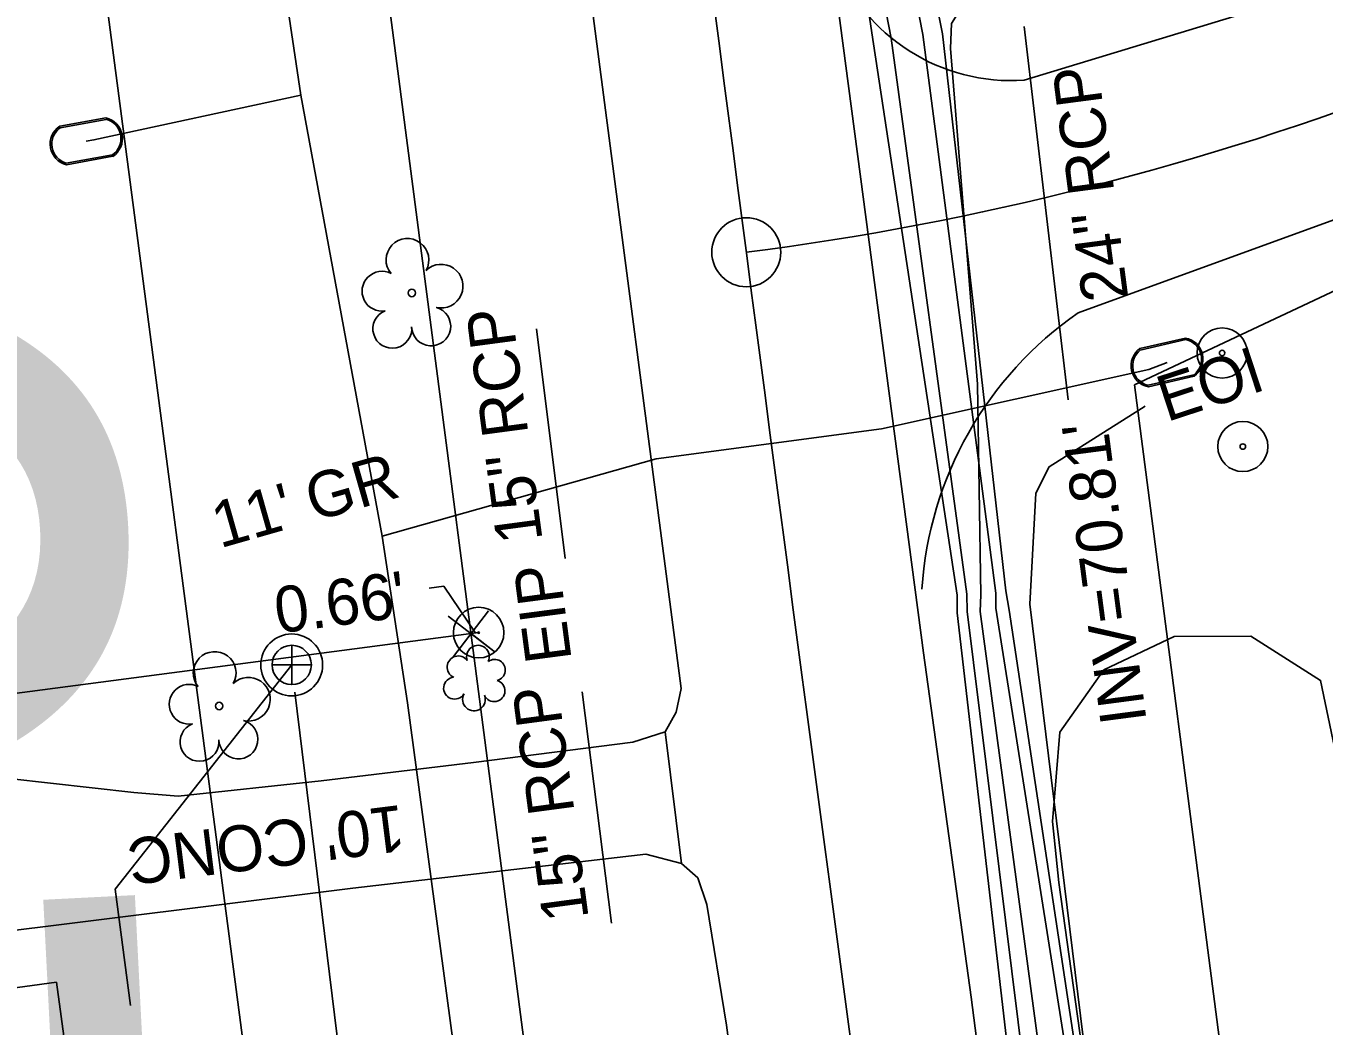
# Model space of a CAD drawing. Extents: x 2364404 to 2371833, y 798876 to 809754.
# Drawn here: x 2368460.1 to 2368573.1, y 806788.8 to 806875.8 of the extents above; entities that cross this region are included whole.
import ezdxf

# ---------------------------------------------------------------- set-up
doc = ezdxf.new("R2010")
doc.units = 0
for name, color, linetype in [('Exist Building', 7, 'Continuous'), ('Exist Horizontal Alignment Direction Label', 7, 'Continuous'), ('Exist Horizontal Alignment Point', 7, 'Continuous'), ('Exist Other Culture Located Object CELL', 7, 'Continuous'), ('Exist Property Corner CELL', 7, 'Continuous'), ('Exist Property Iron Pin CELL', 7, 'Continuous'), ('Exist Property Iron Pin Text', 7, 'Continuous'), ('Exist Property Line', 7, 'Continuous'), ('Exist Property Line Leader', 7, 'Continuous'), ('Exist Property Line Text', 7, 'Continuous'), ('Exist Right of Way Easement Line', 7, 'Continuous'), ('Exist Right of Way Line', 7, 'Continuous'), ('Exist Roads EOP', 7, 'Continuous'), ('Exist Roads EOP Other', 7, 'Continuous'), ('Exist Roads EOP Other Text', 7, 'Continuous'), ('Exist Roads Soil', 7, 'Continuous'), ('Exist Roads Soil Text', 7, 'Continuous'), ('Exist Structure Minor Pipes RCP 15 Inch', 7, 'Continuous'), ('Exist Structure Minor Pipes RCP 15 Inch Text', 7, 'Continuous'), ('Exist Structure Minor Pipes RCP 24 Inch', 7, 'Continuous'), ('Exist Structure Minor Pipes RCP 24 Inch Invert', 7, 'Continuous'), ('Exist Structure Minor Pipes RCP 24 Inch Text', 7, 'Continuous'), ('Exist Utilities Gas UG Line SUE LOS B', 7, 'Continuous'), ('Exist Utilities Other Located Object CELL', 7, 'Continuous'), ('Exist Utilities Sanitary Sewer Manhole CELL', 7, 'Continuous'), ('Exist Utilities Sanitary Sewer Manhole Leader', 7, 'Continuous'), ('Exist Utilities Sanitary Sewer UG Line', 7, 'Continuous'), ('Exist Utilities Telephone UG Cable SUE LOS C', 7, 'Continuous'), ('Exist Utilities Telephone UG Cable SUE LOS C Text', 7, 'Continuous'), ('Exist Utilities Telephone UG FO SUE LOS B', 7, 'Continuous'), ('Exist Utilities Telephone UG FO SUE LOS D', 7, 'Continuous'), ('Exist Utilities TV UG Cable SUE LOS B', 7, 'Continuous'), ('Exist Utilities Water Meter CELL', 7, 'Continuous'), ('Exist Utilities Water UG Line SUE LOS B', 7, 'Continuous'), ('Exist Vegetation Shrub CELL', 7, 'Continuous'), ('Exist Vegetation Tree CELL', 7, 'Continuous'), ('Exist Vegetation Woods Line', 7, 'Continuous'), ('Prop Horizontal Alignment', 7, 'Continuous')]:
    doc.layers.add(name, color=color, linetype=linetype)

msp = doc.modelspace()

# ---------------------------------------------------------------- linework, layer by layer
at = {"layer": 'Exist Building'}
msp.add_lwpolyline([(2368438.39, 806735.97), (2368431.21, 806788.32), (2368462.79, 806792.65), (2368466.23, 806767.5), (2368461.22, 806766.81), (2368464.95, 806739.61)], close=True, dxfattribs=at)
at = {"layer": 'Exist Horizontal Alignment Point'}
msp.add_circle((2368522.8, 806856.13), 3, dxfattribs=at)
at = {"layer": 'Exist Other Culture Located Object CELL'}
for radius in [2.18, 0.24]:
    msp.add_circle((2368565.99, 806839.23), radius, dxfattribs=at)
at = {"layer": 'Exist Property Corner CELL'}
msp.add_line((2368498.87, 806822.96), (2368498.87, 806822.96), dxfattribs=at)
msp.add_lwpolyline([(2368500.39, 806824.94), (2368497.34, 806820.98), (2368498.87, 806822.96), (2368500.85, 806821.44), (2368496.88, 806824.48)], dxfattribs=at)
at = {"layer": 'Exist Property Iron Pin CELL'}
for radius in [2.2, 0.0707]:
    msp.add_circle((2368499.52, 806823.05), radius, dxfattribs=at)
at = {"layer": 'Exist Property Line'}
for p, q in [((2368333.99, 806801.31), (2368498.87, 806822.96)), ((2368498.87, 806822.96), (2368499.52, 806823.05))]:
    msp.add_line(p, q, dxfattribs=at)
at = {"layer": 'Exist Property Line Leader'}
msp.add_lwpolyline([(2368499.22, 806823.05), (2368496.48, 806827.1), (2368495.21, 806826.93)], dxfattribs=at)
at = {"layer": 'Exist Right of Way Easement Line'}
msp.add_line((2368511.71, 806538.64), (2368344.2, 807814.14), dxfattribs=at)
at = {"layer": 'Exist Right of Way Line'}
for p, q in [((2368533.02, 806560.45), (2368368.2, 807827.36)), ((2368556.56, 806844.6), (2369018.27, 807061.53)), ((2368619.17, 806363.33), (2368556.56, 806844.6))]:
    msp.add_line(p, q, dxfattribs=at)
at = {"layer": 'Exist Roads EOP'}
for points in [[(2368562.93, 806637.46), (2368555.74, 806690.75), (2368548.61, 806742.82), (2368542.36, 806791.34), (2368538.21, 806821.28), (2368530.22, 806881.79), (2368518.49, 806971.03), (2368511.29, 807026.45), (2368505.76, 807074.75), (2368500.82, 807111.79), (2368494.06, 807163.04), (2368486.21, 807225.24), (2368486.94, 807228.44), (2368484.21, 807253.24), (2368481.5, 807263.09), (2368479.96, 807275.52), (2368472.82, 807329.17)], [(2368542.08, 806633.94), (2368537.65, 806665.16), (2368536.24, 806665.79), (2368533.02, 806685.33), (2368534.76, 806687.62), (2368527.71, 806739.03), (2368521.09, 806788.9), (2368519.37, 806799.41), (2368518.6, 806801.72), (2368517.16, 806802.97), (2368515.73, 806814.41), (2368516.71, 806816.13), (2368517.13, 806818.19), (2368509.17, 806879.16), (2368497.78, 806964.4), (2368495.51, 806965.25), (2368493.89, 806981.12), (2368495.71, 806983.28), (2368490.79, 807023.19), (2368488.57, 807040.03)]]:
    msp.add_lwpolyline(points, dxfattribs=at)
at = {"layer": 'Exist Roads EOP Other'}
msp.add_line((2368514.07, 806803.78), (2368517.16, 806802.97), dxfattribs=at)
for points in [[(2368515.73, 806814.41), (2368512.94, 806813.51), (2368499.07, 806811.77), (2368485.81, 806810.15), (2368473.38, 806808.82), (2368469.54, 806809.14), (2368458.64, 806810.35), (2368453.39, 806810.8), (2368445.02, 806809.89), (2368429.46, 806807.35)], [(2368514.07, 806803.78), (2368505.33, 806802.78), (2368488.59, 806800.83), (2368455.28, 806796.67), (2368455.88, 806791.71)]]:
    msp.add_lwpolyline(points, dxfattribs=at)
at = {"layer": 'Exist Roads Soil'}
for points in [[(2368546.98, 806871.09), (2368590.6, 806884.38), (2368636.02, 806903.12), (2368685.77, 806924.3), (2368729.9, 806945.5)], [(2368551.68, 806850.87), (2368596.14, 806867.04), (2368645.06, 806889.19), (2368692.28, 806909.13), (2368738.29, 806929.75)]]:
    msp.add_lwpolyline(points, dxfattribs=at)
for centre, radius, start, end in [((2368545.85, 806887.56), 16.51, 200.905, 273.9339), ((2368569.76, 806824.77), 31.75, 124.7105, 176.283)]:
    msp.add_arc(centre, radius, start, end, dxfattribs=at)
at = {"layer": 'Exist Structure Minor Pipes RCP 15 Inch'}
for p, q in [((2368507.04, 806829.5), (2368504.55, 806849.46)), ((2368511.09, 806797.77), (2368508.52, 806817.89))]:
    msp.add_line(p, q, dxfattribs=at)
at = {"layer": 'Exist Structure Minor Pipes RCP 24 Inch'}
msp.add_line((2368546.96, 806875.77), (2368550.79, 806843.3), dxfattribs=at)
at = {"layer": 'Exist Utilities Gas UG Line SUE LOS B'}
msp.add_lwpolyline([(2368565.51, 806627.35), (2368559.18, 806675.74), (2368554.09, 806719.63), (2368549.98, 806751.76), (2368546.89, 806775.18), (2368541.13, 806824.77), (2368541.15, 806826.3), (2368533.73, 806875.2), (2368530.25, 806898.57), (2368522.83, 806953.25), (2368520.6, 806972.93), (2368514.47, 807022.15), (2368508.12, 807071.69), (2368503.05, 807109.35), (2368503.04, 807109.39), (2368501.76, 807120.55), (2368495.27, 807170.09), (2368488.83, 807219.75), (2368482.33, 807269.18), (2368476.59, 807310.66)], dxfattribs=at)
at = {"layer": 'Exist Utilities Other Located Object CELL'}
for radius in [2.18, 0.24]:
    msp.add_circle((2368564.19, 806847.37), radius, dxfattribs=at)
at = {"layer": 'Exist Utilities Sanitary Sewer Manhole CELL'}
msp.add_lwpolyline([(2368483.26, 806821.95), (2368483.26, 806818.53), (2368483.26, 806820.24), (2368484.98, 806820.24), (2368481.55, 806820.24)], dxfattribs=at)
for radius in [2.69, 1.71]:
    msp.add_circle((2368483.26, 806820.24), radius, dxfattribs=at)
at = {"layer": 'Exist Utilities Sanitary Sewer Manhole Leader'}
msp.add_lwpolyline([(2368483.26, 806820.24), (2368467.91, 806800.74), (2368469.24, 806790.61)], dxfattribs=at)
at = {"layer": 'Exist Utilities Sanitary Sewer UG Line'}
msp.add_line((2368483.53, 806817.87), (2368521.16, 806511.46), dxfattribs=at)
at = {"layer": 'Exist Utilities Telephone UG Cable SUE LOS C'}
for points in [[(2368513, 806728.67), (2368513.11, 806729.23), (2368527.58, 806725.8), (2368551.81, 806727.42), (2368553.66, 806732.83), (2368554.05, 806735.47), (2368548.14, 806775.63), (2368542, 806824.9), (2368541.99, 806826.38), (2368535.41, 806874.73), (2368525.92, 806923.45), (2368519.62, 806972.71), (2368513.1, 807021.89), (2368507.14, 807071.19), (2368500.36, 807120.72), (2368487.41, 807219.56), (2368485.62, 807270.73), (2368476.5, 807319.29)], [(2368512.76, 806728.82), (2368513.23, 806728.83), (2368526.6, 806730.3), (2368554.19, 806730.87), (2368555.55, 806735.53), (2368549.73, 806775.94), (2368543.15, 806824.88), (2368543.19, 806826.35), (2368542.9, 806844.67), (2368540.57, 806873.85), (2368540.65, 806876.02), (2368542.68, 806879.28), (2368552.82, 806878.65), (2368578.3, 806883.33), (2368609.68, 806897.03), (2368634.38, 806908.76), (2368649.63, 806915.88), (2368651.51, 806917.09), (2368652, 806919.33), (2368650.03, 806922.76), (2368650.32, 806923.36)]]:
    msp.add_lwpolyline(points, dxfattribs=at)
at = {"layer": 'Exist Utilities Telephone UG FO SUE LOS B'}
msp.add_lwpolyline([(2368557.66, 806726.62), (2368552.25, 806776.28), (2368544.5, 806825.17), (2368544.52, 806826.49), (2368538.15, 806875.06), (2368528.53, 806924.12), (2368522.67, 806972.9), (2368516.86, 807022.32), (2368510.19, 807071.54), (2368510.15, 807071.85), (2368503.82, 807121.23), (2368497.45, 807169.98), (2368490.99, 807219.7), (2368486.98, 807243.03), (2368483.26, 807270.12), (2368478.16, 807319.19)], dxfattribs=at)
at = {"layer": 'Exist Utilities Telephone UG FO SUE LOS D'}
msp.add_lwpolyline([(2368570.42, 806627.22), (2368563.79, 806676.05), (2368559.26, 806726.79), (2368553, 806776.39), (2368545.68, 806825.01), (2368545.37, 806826.67), (2368539.86, 806875.13), (2368530.01, 806924.21), (2368524.34, 806972.87), (2368518.19, 807022.38), (2368511.17, 807071.48), (2368504.8, 807121.29), (2368498.76, 807170.03), (2368493.38, 807219.79), (2368488.92, 807243.04), (2368484.81, 807270.66), (2368473.51, 807368.34)], dxfattribs=at)
at = {"layer": 'Exist Utilities TV UG Cable SUE LOS B'}
msp.add_lwpolyline([(2368511.74, 806730.95), (2368526.2, 806733.08), (2368549.61, 806740.43), (2368557.41, 806743.28), (2368553.5, 806776.53), (2368547.46, 806825.52), (2368547.99, 806835.17), (2368549.16, 806837.48), (2368557.51, 806842.73)], dxfattribs=at)
at = {"layer": 'Exist Utilities Water Meter CELL'}
for p, q in [((2368465.39, 806865.78), (2368465.39, 806865.78)), ((2368559.41, 806846.55), (2368559.41, 806846.55))]:
    msp.add_line(p, q, dxfattribs=at)
for points in [[(2368463.08, 806867.09), (2368467.09, 806867.82)], [(2368463.11, 806866.95), (2368467.12, 806867.68)], [(2368467.68, 806864.61), (2368463.65, 806863.87)], [(2368467.7, 806864.48), (2368463.67, 806863.74)], [(2368557.04, 806847.75), (2368561.01, 806848.66)], [(2368557.07, 806847.62), (2368561.04, 806848.53)], [(2368561.74, 806845.48), (2368557.75, 806844.56)], [(2368561.77, 806845.35), (2368557.78, 806844.43)]]:
    msp.add_lwpolyline(points, dxfattribs=at)
for centre, radius, start, end in [((2368466.67, 806866.01), 1.86, 303.9851, 76.6451), ((2368466.68, 806866.02), 1.73, 305.4639, 75.2096), ((2368464.11, 806865.54), 1.86, 123.5148, 256.3162), ((2368464.12, 806865.54), 1.73, 125.6377, 254.1191), ((2368560.66, 806846.84), 1.86, 306.5926, 79.2527), ((2368560.68, 806846.84), 1.73, 308.0715, 77.8171), ((2368558.13, 806846.25), 1.86, 126.1223, 258.9237), ((2368558.14, 806846.25), 1.73, 128.2452, 256.7266)]:
    msp.add_arc(centre, radius, start, end, dxfattribs=at)
at = {"layer": 'Exist Utilities Water UG Line SUE LOS B'}
for points in [[(2368519.2, 806620.08), (2368510.97, 806683.25), (2368505.65, 806723.63), (2368499.9, 806767.95), (2368493.34, 806816.93), (2368491.14, 806831.44), (2368484.04, 806869.78), (2368477.82, 806911.63), (2368472.48, 806959.83), (2368471.08, 806975.35), (2368467.91, 807014.19), (2368461.16, 807070.94), (2368455.32, 807116.26), (2368449.6, 807161.65), (2368446.12, 807187.28), (2368441.35, 807211.9), (2368441.09, 807221.64), (2368437.56, 807243.96), (2368435.61, 807263.12), (2368428.93, 807315.03)], [(2368465.39, 806865.78), (2368466.06, 806865.9), (2368484.04, 806869.78)], [(2368491.14, 806831.44), (2368514.96, 806838.17), (2368534.56, 806840.77), (2368557.81, 806845.93), (2368559.41, 806846.55)]]:
    msp.add_lwpolyline(points, dxfattribs=at)
at = {"layer": 'Exist Vegetation Shrub CELL'}
msp.add_line((2368499.23, 806818.92), (2368499.23, 806818.92), dxfattribs=at)
for centre, radius, start, end in [((2368499.46, 806820.96), 0.99, 334.8391, 200.4717), ((2368497.75, 806820.05), 0.968, 35.8908, 245.4216), ((2368500.91, 806819.79), 0.929, 284.4567, 126.0861), ((2368497.43, 806818.22), 0.955, 95.1099, 327.9534), ((2368500.87, 806817.99), 0.937, 204.9913, 73.4601), ((2368499.11, 806817.24), 0.984, 151.2797, 21.387)]:
    msp.add_arc(centre, radius, start, end, dxfattribs=at)
at = {"layer": 'Exist Vegetation Tree CELL'}
for p, q in [((2368493.71, 806852.59), (2368493.71, 806852.59)), ((2368476.95, 806816.67), (2368476.95, 806816.67))]:
    msp.add_line(p, q, dxfattribs=at)
for centre in [(2368493.71, 806852.59), (2368476.95, 806816.67)]:
    msp.add_circle(centre, 0.326, dxfattribs=at)
for centre, radius, start, end in [((2368493.33, 806855.46), 1.86, 330.1651, 219.7134), ((2368491.11, 806852.74), 1.73, 62.6636, 279.3457), ((2368496.26, 806853.18), 1.9, 257.1011, 134.1999), ((2368492.01, 806849.47), 1.69, 111.5671, 6.231), ((2368495.39, 806849.69), 1.7, 181.2822, 74.56), ((2368476.56, 806819.54), 1.86, 330.1651, 219.7134), ((2368479.49, 806817.26), 1.9, 257.1011, 134.1999), ((2368474.34, 806816.82), 1.73, 62.6636, 279.3457), ((2368475.24, 806813.55), 1.69, 111.5671, 6.231), ((2368478.62, 806813.77), 1.7, 181.2822, 74.56)]:
    msp.add_arc(centre, radius, start, end, dxfattribs=at)
at = {"layer": 'Exist Vegetation Woods Line'}
msp.add_lwpolyline([(2368576.79, 806799.61), (2368585.43, 806733.99), (2368583.77, 806729.88), (2368578.39, 806726.54), (2368572.47, 806725.9), (2368565.94, 806725.32), (2368561.71, 806727.54), (2368559.61, 806732.42), (2368550, 806801.33), (2368549.44, 806806.63), (2368550.08, 806814.39), (2368553.91, 806819.82), (2368560.02, 806822.71), (2368566.69, 806822.74), (2368572.75, 806818.89), (2368576.79, 806799.61)], dxfattribs=at)
at = {"layer": 'Prop Horizontal Alignment'}
for centre, radius, start, end in [((2391111.53, 809808.52), 22780.85, 187.308437, 187.801711), ((2368490.98, 807104.09), 250, 277.3135, 291.2149)]:
    msp.add_arc(centre, radius, start, end, dxfattribs=at)

# ---------------------------------------------------------------- texts
at = {"layer": 'Exist Horizontal Alignment Direction Label'}
msp.add_text('BL-110', height=73.5, rotation=92.9054, dxfattribs=at).set_placement((2368482.67, 806543.08))
at = {"layer": 'Exist Property Iron Pin Text'}
msp.add_text('EIP', height=4, rotation=97.4798, dxfattribs=at).set_placement((2368507.62, 806820.69))
at = {"layer": 'Exist Property Line Text'}
msp.add_text("0.66'", height=4, rotation=7.4817, dxfattribs=at).set_placement((2368482.04, 806822.97))
at = {"layer": 'Exist Roads EOP Other Text'}
msp.add_text("10' CONC", height=4, rotation=187.158, dxfattribs=at).set_placement((2368492.81, 806808.08))
at = {"layer": 'Exist Roads Soil Text'}
msp.add_text("11' GR", height=4, rotation=15.928, dxfattribs=at).set_placement((2368477.02, 806830.37))
at = {"layer": 'Exist Structure Minor Pipes RCP 15 Inch Text'}
for p in [(2368505.09, 806831.09), (2368509.1, 806798.21)]:
    msp.add_text('15" RCP', height=4, rotation=97.5936, dxfattribs=at).set_placement(p)
at = {"layer": 'Exist Structure Minor Pipes RCP 24 Inch Invert'}
msp.add_text("INV=70.81'", height=4, rotation=97.4798, dxfattribs=at).set_placement((2368557.63, 806815.35))
at = {"layer": 'Exist Structure Minor Pipes RCP 24 Inch Text'}
msp.add_text('24" RCP', height=4, rotation=97.4798, dxfattribs=at).set_placement((2368556.04, 806852.13))
at = {"layer": 'Exist Utilities Telephone UG Cable SUE LOS C Text'}
msp.add_text('EOI', height=4, rotation=18.1399, dxfattribs=at).set_placement((2368559.37, 806841.35))

doc.saveas('drawing.dxf')
